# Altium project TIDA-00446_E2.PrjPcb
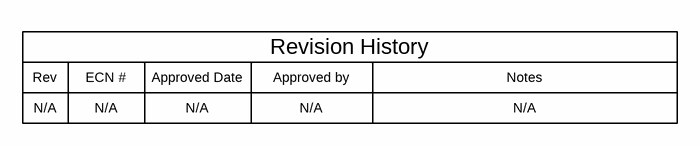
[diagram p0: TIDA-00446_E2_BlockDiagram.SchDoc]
CopyrightYear: 2015; EVM_Orderable: N/A; PCB_Layout: Avinash N; PCB_Rev: E2; PRJ_Customer: Public Release; PRJ_Engineer: Pawan N; PRJ_Number: TIDA-00446; PRJ_Title: 6 channel Isolated Gate driver; SCH_Rev: E2; TechSupport: http://www.ti.com/support; TID: TIDA-00446
5 sheets, 193 parts. Net scope: flat (ports and power ports of the same name join across sheets).
Board file: TIDA-00446_E2.PcbDoc
Sheets:
  TIDA-00446_E2_BlockDiagram.SchDoc
  TIDA-00446_E2_GateDriverPhaseU.SchDoc
  TIDA-00446_E2_GateDriverPhaseV.SchDoc
  TIDA-00446_E2_GateDriverPhaseW.SchDoc
  TIDA-00446_E2_TID_Hardware.SchDoc

## Sheet TIDA-00446_E2_BlockDiagram.SchDoc: Block Diagram
size 431 x 279 mm; Date: Not shown in title block; ApprovedBy: Not shown in title block; CheckedBy: Not shown in title block; Author: Not shown in title block; CompanyName: Not shown in title block; DrawnBy: Pawan N; Engineer: Not shown in title block; Organization: Not shown in title block; Address1: Not shown in title block; Address2: Not shown in title block; Address3: Not shown in title block; Address4: Not shown in title block; DocumentNumber: 1; Revision: Use project parameter SCH_Rev; SheetNumber: 1; SheetTotal: 5; PageSetup: Record=PageOptions¦CenterHorizontal=True¦CenterVertical=True¦PrintScale=1.00¦XCorrection=1.00¦YCorrection=1.00¦PrintKind=0¦BorderSize=5000000¦LeftOffset=0¦BottomOffset=0¦Orientation=2¦PaperLength=1000¦PaperWidth=1000¦Scale=100¦PaperSource=15¦PrintQuality=600¦MediaType=1¦DitherType=10¦PaperKind=Letter¦PrintScaleMode=1

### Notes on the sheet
- Rev
- N/A
- ECN #
- Approved Date
- Approved by
- Revision History
- Notes

## Sheet TIDA-00446_E2_GateDriverPhaseU.SchDoc: Power supply and Gate driver
size 431 x 279 mm; Date: Not shown in title block; ApprovedBy: Not shown in title block; CheckedBy: Not shown in title block; Author: Not shown in title block; CompanyName: Not shown in title block; DrawnBy: Pawan N; Engineer: Not shown in title block; Organization: Not shown in title block; Address1: Not shown in title block; Address2: Not shown in title block; Address3: Not shown in title block; Address4: Not shown in title block; DocumentNumber: 1; Revision: Use project parameter SCH_Rev; SheetNumber: 2; SheetTotal: 5; PageSetup: Record=PageOptions¦CenterHorizontal=True¦CenterVertical=True¦PrintScale=1.00¦XCorrection=1.00¦YCorrection=1.00¦PrintKind=0¦BorderSize=5000000¦LeftOffset=0¦BottomOffset=0¦Orientation=2¦PaperLength=1000¦PaperWidth=1000¦Scale=100¦PaperSource=15¦PrintQuality=600¦MediaType=1¦DitherType=10¦PaperKind=Letter¦PrintScaleMode=1
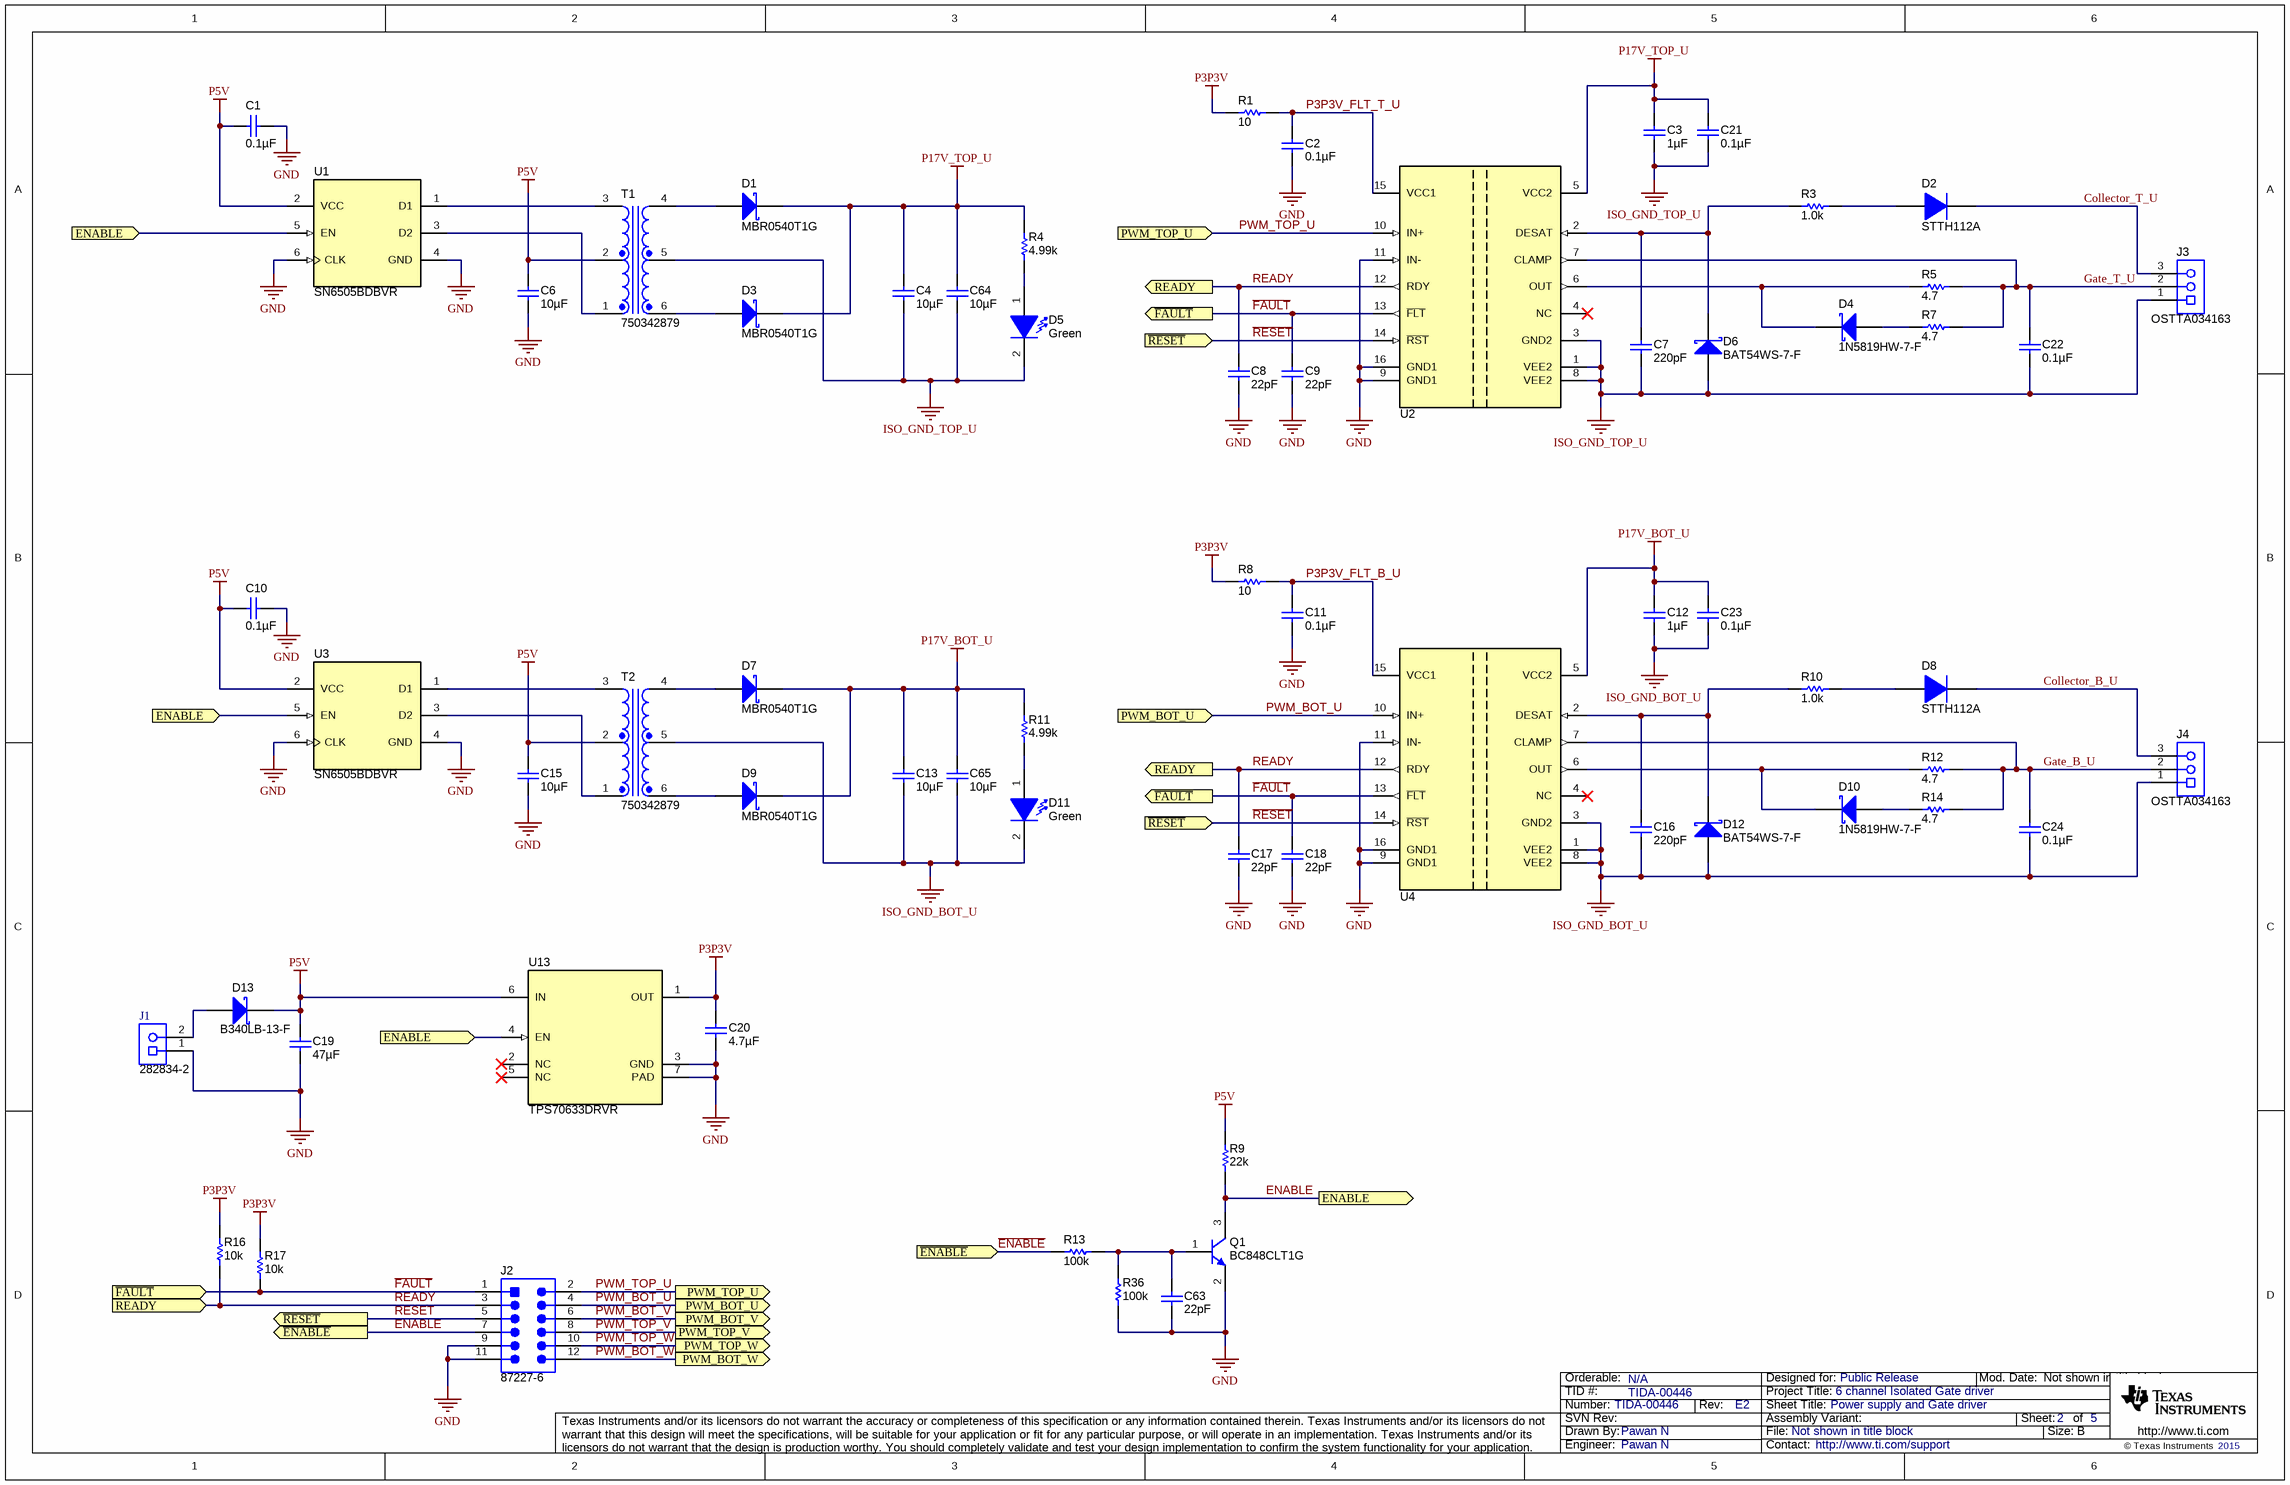
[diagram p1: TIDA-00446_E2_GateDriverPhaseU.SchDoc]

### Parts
C1  ValueDisplayed: 0.1µF  [0603]  (hidden comment: GRM188R71H104KA93D)
C2  ValueDisplayed: 0.1µF  [0603]  (hidden comment: GRM188R71H104KA93D)
C3  ValueDisplayed: 1µF  [0603]  (hidden comment: C1608X7R1V105K080AC)
C4  ValueDisplayed: 10µF  [1206_190]  (hidden comment: C3216X7R1V106K160AC)
C6  ValueDisplayed: 10µF  [0603]  (hidden comment: GRM188C81A106MA73D)
C7  ValueDisplayed: 220pF  [0402]  (hidden comment: C1005X7R1H104K050BB)
C8  ValueDisplayed: 22pF  [0402]  (hidden comment: GRM1555C1H220FA01D)
C9  ValueDisplayed: 22pF  [0402]  (hidden comment: GRM1555C1H220FA01D)
C10  ValueDisplayed: 0.1µF  [0603]  (hidden comment: GRM188R71H104KA93D)
C11  ValueDisplayed: 0.1µF  [0603]  (hidden comment: GRM188R71H104KA93D)
C12  ValueDisplayed: 1µF  [0603]  (hidden comment: C1608X7R1V105K080AC)
C13  ValueDisplayed: 10µF  [1206_190]  (hidden comment: C3216X7R1V106K160AC)
C15  ValueDisplayed: 10µF  [0603]  (hidden comment: GRM188C81A106MA73D)
C16  ValueDisplayed: 220pF  [0402]  (hidden comment: GRM155R71H221KA01D)
C17  ValueDisplayed: 22pF  [0402]  (hidden comment: GRM1555C1H220FA01D)
C18  ValueDisplayed: 22pF  [0402]  (hidden comment: GRM1555C1H220FA01D)
C19  ValueDisplayed: 47µF  [1210]  (hidden comment: GRM32ER61C476ME15L)
C20  ValueDisplayed: 4.7µF  [0603]  (hidden comment: C1608X7S1A475K080AC)
C21  ValueDisplayed: 0.1µF  [0603]  (hidden comment: GRM188R71H104KA93D)
C22  ValueDisplayed: 0.1µF  [0603]  (hidden comment: GRM188R71H104KA93D)
C23  ValueDisplayed: 0.1µF  [0603]  (hidden comment: GRM188R71H104KA93D)
C24  ValueDisplayed: 0.1µF  [0603]  (hidden comment: GRM188R71H104KA93D)
C63  ValueDisplayed: 22pF  [0402]  (hidden comment: GRM1555C1H220FA01D)
C64  ValueDisplayed: 10µF  [1206_190]  (hidden comment: C3216X7R1V106K160AC)
C65  ValueDisplayed: 10µF  [1206_190]  (hidden comment: C3216X7R1V106K160AC)
D1  MBR0540T1G  [SOD-123]
D2  STTH112A  [SMA]
D3  MBR0540T1G  [SOD-123]
D4  1N5819HW-7-F  [SOD-123]
D5  value Green  [LG L29K_GREEN]  (hidden comment: LG L29K-G2J1-24-Z)
D6  BAT54WS-7-F  [sod-323]
D7  MBR0540T1G  [SOD-123]
D8  STTH112A  [SMA]
D9  MBR0540T1G  [SOD-123]
D10  1N5819HW-7-F  [SOD-123]
D11  value Green  [LG L29K_GREEN]  (hidden comment: LG L29K-G2J1-24-Z)
D12  BAT54WS-7-F  [sod-323]
D13  B340LB-13-F  [SMB]
J1  282834-2  [TEC_282834-2]
J2  87227-6  [CONN_87227-6]
J3  OSTTA034163  [On-Shore_OSTTA034163]
J4  OSTTA034163  [On-Shore_OSTTA034163]
Q1  BC848CLT1G  [SOT-23]
R1  ValueDisplayed: 10  [0402]  (hidden comment: CRCW040210R0JNED)
R3  ValueDisplayed: 1.0k  [0805_HV]  (hidden comment: CRCW08051K00JNEA)
R4  ValueDisplayed: 4.99k  [0402]  (hidden comment: CRCW04024K99FKED)
R5  ValueDisplayed: 4.7  [1206]  (hidden comment: RPC1206JT4R70)
R7  ValueDisplayed: 4.7  [0805_HV]  (hidden comment: RPC0805JT4R70)
R8  ValueDisplayed: 10  [0402]  (hidden comment: RC0402JR-070RL)
R9  ValueDisplayed: 22k  [0603]  (hidden comment: CRCW060322K0JNEA)
R10  ValueDisplayed: 1.0k  [0805_HV]  (hidden comment: CRCW08051K00JNEA)
R11  ValueDisplayed: 4.99k  [0402]  (hidden comment: CRCW04024K99FKED)
R12  ValueDisplayed: 4.7  [1206]  (hidden comment: RPC1206JT4R70)
R13  ValueDisplayed: 100k  [0603]  (hidden comment: CRCW0603100KJNEA)
R14  ValueDisplayed: 4.7  [0805_HV]  (hidden comment: RPC0805JT4R70)
R16  ValueDisplayed: 10k  [0402]  (hidden comment: CRCW040210R0JNED)
R17  ValueDisplayed: 10k  [0402]  (hidden comment: CRCW040210R0JNED)
R36  ValueDisplayed: 100k  [0603]  (hidden comment: CRCW0603100KJNEA)
T1  750342879  [Wurth_750342879]
T2  750342879  [Wurth_750342879]
U1  SN6505BDBVR  [DBV0006A_N]
U2  ISO5851DWR  [DW0016B_N]  (value not drawn)
U3  SN6505BDBVR  [DBV0006A_N]
U4  ISO5851DWR  [DW0016B_N]  (value not drawn)
U13  TPS70633DRVR  [DRV0006A]

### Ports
ENABLE (in), ENABLE (out), PWM_BOT_U (in), PWM_BOT_U (out), PWM_BOT_V (out), PWM_BOT_W (out), PWM_TOP_U (in), PWM_TOP_U (out), PWM_TOP_V (out), PWM_TOP_W (out), READY (in), READY (out), ~{ENABLE} (in), ~{ENABLE} (out), ~{FAULT} (in), ~{FAULT} (out), ~{RESET} (in), ~{RESET} (out)

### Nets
GND: C1.1 C2.2 C6.2 C8.2 C9.2 C10.1 C11.2 C15.2 C17.2 C18.2 C19.2 C20.2 C63.2 J1.1 J2.9 J2.11 Q1.2(E) R36.1 U1.4(GND) U1.6(CLK) U2.9(GND1) U2.11(IN-) U2.16(GND1) U3.4(GND) U3.6(CLK) U4.9(GND1) U4.11(IN-) U4.16(GND1) U13.3(GND) U13.7(PAD)
ISO_GND_BOT_U: C12.2 C13.2 C16.2 C23.2 C24.2 C65.2 D11.2(K) D12.2(A) J4.1 T2.5 U4.1(VEE2) U4.3(GND2) U4.8(VEE2)
ISO_GND_TOP_U: C3.2 C4.2 C7.2 C21.2 C22.2 C64.2 D5.2(K) D6.2(A) J3.1 T1.5 U2.1(VEE2) U2.3(GND2) U2.8(VEE2)
P3P3V: C20.1 R1.1 R8.1 R16.2 R17.2 U13.1(OUT)
P5V: C1.2 C6.1 C10.2 C15.1 C19.1 D13.1(K) R9.2 T1.2 T2.2 U1.2(VCC) U3.2(VCC) U13.6(IN)
P17V_BOT_U: C12.1 C13.1 C23.1 C65.1 D7.1(K) D9.1(K) R11.2 U4.5(VCC2)
P17V_TOP_U: C3.1 C4.1 C21.1 C64.1 D1.1(K) D3.1(K) R4.2 U2.5(VCC2)
~{FAULT}: C9.1 C18.1 J2.1 R17.1 U2.13(~{FLT}) U4.13(~{FLT}) ; port ~{FAULT}
~{RESET}: J2.5 U2.14(~{RST}) U4.14(~{RST}) ; port ~{RESET}
Collector_B_U: D8.1(K) J4.3
Collector_T_U: D2.1(K) J3.3
~{ENABLE}: J2.7 R13.1 ; port ~{ENABLE}
ENABLE: Q1.3(C) R9.1 U1.5(EN) U3.5(EN) U13.4(EN) ; port ENABLE
Gate_B_U: C24.1 J4.2 R12.2 R14.2 U4.7(CLAMP)
Gate_T_U: C22.1 J3.2 R5.2 R7.2 U2.7(CLAMP)
P3P3V_FLT_B_U: C11.1 R8.2 U4.15(VCC1)
P3P3V_FLT_T_U: C2.1 R1.2 U2.15(VCC1)
PWM_BOT_U: J2.4 U4.10(IN+) ; port PWM_BOT_U
PWM_BOT_V: J2.6 ; port PWM_BOT_V
PWM_BOT_W: J2.12 ; port PWM_BOT_W
PWM_TOP_U: J2.2 U2.10(IN+) ; port PWM_TOP_U
PWM_TOP_V: J2.8 ; port PWM_TOP_V
PWM_TOP_W: J2.10 ; port PWM_TOP_W
READY: C8.1 C17.1 J2.3 R16.1 U2.12(RDY) U4.12(RDY) ; port READY
NetC7_1: C7.1 D6.1(K) R3.1 U2.2(DESAT)
NetC16_1: C16.1 D12.1(K) R10.1 U4.2(DESAT)
NetC63_1: C63.1 Q1.1(B) R13.2 R36.2
NetD1_2: D1.2(A) T1.4
NetD2_2: D2.2(A) R3.2
NetD3_2: D3.2(A) T1.6
NetD4_1: D4.1(K) R5.1 U2.6(OUT)
NetD4_2: D4.2(A) R7.1
NetD5_1: D5.1(A) R4.1
NetD7_2: D7.2(A) T2.4
NetD8_2: D8.2(A) R10.2
NetD9_2: D9.2(A) T2.6
NetD10_1: D10.1(K) R12.1 U4.6(OUT)
NetD10_2: D10.2(A) R14.1
NetD11_1: D11.1(A) R11.1
NetD13_2: D13.2(A) J1.2
NetT1_1: T1.1 U1.3(D2)
NetT1_3: T1.3 U1.1(D1)
NetT2_1: T2.1 U3.3(D2)
NetT2_3: T2.3 U3.1(D1)

Not connected (* = marked no-connect by the designer): U2 4(NC)*; U4 4(NC)*; U13 2(NC)* 5(NC)*

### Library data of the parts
C1 C2 C10 C11 C21-C24 = GRM188R71H104KA93D: CAP, CERM, 0.1 µF, 50 V, +/- 10%, X7R, 0603; Manufacturer: MuRata; Polarized: N; CompType: Capacitor; Value: 0.1uF; U/M: EA; Cap_F: 0.0000001; Tolerance_%: 10; Value1: Unknown; VDC_V: 50; Value2: 50V; TaMin_C: -55; TaMax_C: 125
C3 C12 = C1608X7R1V105K080AC: CAP, CERM, 1 µF, 30 V, +/- 10%, X7R, 0603; Manufacturer: TDK; Polarized: N; CompType: Capacitor; Value: 1uF; U/M: EA; Cap_F: 0.000001; Tolerance_%: 10; Value1: Unknown; VDC_V: 30; Value2: 30V; TaMin_C: -55; TaMax_C: 125; AEC Category: Q200
C4 C13 C64 C65 = C3216X7R1V106K160AC: CAP, CERM, 10 µF, 35 V, +/- 10%, X7R, 1206_190; Manufacturer: TDK; Polarized: N; CompType: Capacitor; Value: 10uF; U/M: EA; Cap_F: 0.00001; Tolerance_%: 10; Value1: Unknown; VDC_V: 35; Value2: 35V; TaMin_C: -55; TaMax_C: 125; Cap_Case: 1206; AEC Category: Q200
C6 C15 = GRM188C81A106MA73D: CAP, CERM, 10 µF, 10 V, +/- 20%, X6S, 0603; Manufacturer: MuRata; Polarized: N; CompType: Capacitor; Value: 10uF; U/M: EA; Cap_F: 0.00001; Tolerance_%: 20; Value1: Unknown; VDC_V: 10; Value2: 10V; TaMin_C: -55; TaMax_C: 105; AEC Category: Q200
C7 C16 = GRM155R71H221KA01D: CAP, CERM, 220 pF, 50 V, +/- 10%, X7R, 0402; Manufacturer: MuRata; Polarized: N; CompType: Capacitor; Value: 220pF; U/M: EA; Cap_F: 0.00000000022; Tolerance_%: 10; Value1: Unknown; VDC_V: 50; Value2: 50V; TaMin_C: -55; TaMax_C: 125
C8 C9 C17 C18 C63 = GRM1555C1H220FA01D: CAP, CERM, 22 pF, 50 V, +/- 1%, C0G/NP0, 0402; Manufacturer: MuRata; Polarized: N; CompType: Capacitor; Value: 22pF; U/M: EA; Cap_F: 0.000000000022; Tolerance_%: 1; Value1: Unknown; VDC_V: 50; Value2: 50V; TaMin_C: -55; TaMax_C: 125; AEC Category: Q200
C19 = GRM32ER61C476ME15L: CAP, CERM, 47 µF, 16 V, +/- 20%, X5R, 1210; Manufacturer: MuRata; Polarized: N; CompType: Capacitor; Value: 47uF; U/M: EA; Cap_F: 0.000047; Tolerance_%: 20; ESR_ohm: 0.002; Value1: 0.002 ohm; VDC_V: 16; Value2: 16V; TaMin_C: -55; TaMax_C: 85; AEC Category: Q200
C20 = C1608X7S1A475K080AC: CAP, CERM, 4.7 µF, 10 V, +/- 10%, X7S, 0603; Manufacturer: TDK; Polarized: N; CompType: Capacitor; Value: 4.7uF; U/M: EA; Cap_F: 0.0000047; Tolerance_%: 10; Value1: Unknown; Value2: 10V; TaMin_C: -55; TaMax_C: 125; AEC Category: Q200
D1 D3 D7 D9 = MBR0540T1G: Diode, Schottky, 40 V, 0.5 A, SOD-123; Manufacturer: ON Semiconductor; U/M: EA; Vf_V: 0.51; Value: 40V; Value1: 0.5A; Value2: 0.51V; Io_A: 0.5; Vr_V: 40; TJmax_C: 150; RJC_CperW: 118
D2 D8 = STTH112A: Diode, Ultrafast, 1200 V, 1 A, SMA; Manufacturer: STMicroelectronics; U/M: EA; Vf_V: 1.9; Value: 1200V; Value1: 1A; Value2: 1.9V; Io_A: 1; Vr_V: 1200; TJmax_C: 175; AEC Category: Q101; AEC Qualified: N
D4 D10 = 1N5819HW-7-F: Diode, Schottky, 40 V, 1 A, SOD-123; Manufacturer: Diodes Inc.; U/M: EA; Vf_V: 0.45; Value: 40V; Value1: 1A; Value2: 0.45V; Io_A: 1; Vr_V: 40; TJmax_C: 125
D5 D11 = LG L29K-G2J1-24-Z: LED, Green, SMD; Manufacturer: OSRAM; Vf_V: 1.7; Value2: 1.7V; Io_A: 0.002; Tjmax_C: 110; Value1: W; U/M: EA
D6 D12 = BAT54WS-7-F: Diode, Schottky, 30 V, 0.2 A, SOD-323; Manufacturer: Diodes Inc.; U/M: EA; Vf_V: 0.7; Value: 30V; Value1: 0.2A; Value2: 0.7V; Io_A: 0.2; Vr_V: 30; TJmax_C: 125
D13 = B340LB-13-F: Diode, Schottky, 40 V, 3 A, SMB; Manufacturer: Diodes Inc.; U/M: EA; Vf_V: 0.45; Value: 40V; Value1: 3A; Value2: 0.45V; Io_A: 3; Vr_V: 40; TJmax_C: 125; RJC_CperW: 25; AEC Category: Q101
J1 = 282834-2: Terminal Block, 2x1, 2.54mm, TH; Manufacturer: TE Connectivity; SymbolCreator: a0412235; U/M: EA
J2 = 87227-6: Header, 100mil, 6x2, Gold, TH; Manufacturer: TE Connectivity; SymbolCreator: a0412235; U/M: EA
J3 J4 = OSTTA034163: Terminal Block, 3x1, 5.08 mm, TH; Manufacturer: On-Shore Technology; SymbolCreator: a0412235; U/M: EA
Q1 = BC848CLT1G, ON Semiconductor: Transistor, NPN, 30 V, 0.1 A, SOT-23; CompType: BJT; PNP: 0; NPN: 1; Vceo_V: 30; Vcesat1_V: 0.7; Value: 30 V; IcRated_A: 0.1; Value1: 0.1 A; HfeMax: 800; TaMin_C: -55; TaMax_C: 150; U/M: EA
R1 R8 = CRCW040210R0JNED: RES, 10, 5%, 0.063 W, 0402; Manufacturer: Vishay-Dale; CompType: Resistor; Value: 10; Value_Code: 10R0; Tolerance_%: 5; Power_W: 0.063; Value2: 0.063W; VDC_V: 50; TempCo: 200 ppm/C; EIA_Code: E24; U/M: EA
R3 R10 = CRCW08051K00JNEA: RES, 1.0 k, 5%, 0.125 W, 0805; Manufacturer: Vishay-Dale; CompType: Resistor; Value: 1.0k; Res_ohm: 1000; Value_Code: 1k00; Tolerance_%: 5; Power_W: 0.125; Value2: 0.125W; VDC_V: 150; TempCo: 200 ppm/C; EIA_Code: E24; U/M: EA
R4 R11 = CRCW04024K99FKED: RES, 4.99 k, 1%, 0.063 W, 0402; Manufacturer: Vishay-Dale; CompType: Resistor; Value: 4.99k; Res_ohm: 4990; Value_Code: 4k99; Tolerance_%: 1; Power_W: 0.063; Value2: 0.063W; VDC_V: 50; TempCo: 100 ppm/C; EIA_Code: E96; U/M: EA
R5 R12 = RPC1206JT4R70: RES, 4.7, 5%, 0.33 W, 1206; Manufacturer: Stackpole Electronics Inc; CompType: Resistor; Value: 4.7; Value_Code: 4R70; Tolerance_%: 5; Power_W: 0.33; Value2: 0.33W; TempCo: 200 ppm/C; EIA_Code: E24; U/M: EA; AEC Category: Q200; AEC Qualified: N
R7 R14 = RPC0805JT4R70: RES, 4.7, 5%, 0.25 W, 0805; Manufacturer: Stackpole Electronics Inc; CompType: Resistor; Value: 4.7; Value_Code: 4R70; Tolerance_%: 5; Power_W: 0.25; Value2: 0.25W; TempCo: 200 ppm/C; EIA_Code: E24; U/M: EA; AEC Category: Q200; AEC Qualified: N
R9 = CRCW060322K0JNEA: RES, 22 k, 5%, 0.1 W, 0603; Manufacturer: Vishay-Dale; CompType: Resistor; Value: 22k; Res_ohm: 22000; Value_Code: 22k0; Tolerance_%: 5; Power_W: 0.1; Value2: 0.1W; VDC_V: 75; TempCo: 200 ppm/C; EIA_Code: E24; U/M: EA
R13 R36 = CRCW0603100KJNEA: RES, 100 k, 5%, 0.1 W, 0603; Manufacturer: Vishay-Dale; CompType: Resistor; Value: 100k; Res_ohm: 100000; Tolerance_%: 5; Power_W: 0.1; Value2: 0.1W; VDC_V: 75; TempCo: 200 ppm/C; EIA_Code: E24; U/M: EA; AEC Category: Q200
R16 R17 = CRCW040210K0JNED: RES, 10 k, 5%, 0.063 W, 0402; Manufacturer: Vishay-Dale; CompType: Resistor; Value: 10k; Res_ohm: 10000; Value_Code: 10k0; Tolerance_%: 5; Power_W: 0.063; Value2: 0.063W; VDC_V: 50; TempCo: 200 ppm/C; EIA_Code: E24; U/M: EA
T1 T2 = 750342879: Transformer, 50 uH, SMT; Manufacturer: Wurth Elektronik; SymbolCreator: Altium; Value: 50 uH; U/M: EA
U1 U3 = SN6505BDBVR: LOW-NOISE 1A TRANSFORMER DRIVERS FOR ISOLATED POWER SUPPLIES, DBV0006A; Alternate PartNumber: SN6505BDBVT; Manufacturer: Texas Instruments; SymbolCreator: Altium; CompType: IC; U/M: EA
U2 U4 = ISO5851DWR: High-CMTI 2.5-A / 5-A Isolated IGBT, MOSFET Gate Driver with Active Safety Features, DW0016B; Manufacturer: Texas Instruments; SymbolCreator: Altium; CompType: IC; U/M: EA
U13 = TPS70633DRVR: 150-mA, 6.5-V, 1-uA IQ Voltage Regulators with Enable, DRV0006A; Alternate PartNumber: TPS70633DRVT; Manufacturer: Texas Instruments; SymbolCreator: Altium; CompType: IC; U/M: EA

## Sheet TIDA-00446_E2_GateDriverPhaseV.SchDoc: Power supply and Gate driver
size 431 x 279 mm; Date: Not shown in title block; ApprovedBy: Not shown in title block; CheckedBy: Not shown in title block; Author: Not shown in title block; CompanyName: Not shown in title block; DrawnBy: Pawan N; Engineer: Not shown in title block; Organization: Not shown in title block; Address1: Not shown in title block; Address2: Not shown in title block; Address3: Not shown in title block; Address4: Not shown in title block; DocumentNumber: 1; Revision: Use project parameter SCH_Rev; SheetNumber: 3; SheetTotal: 5; PageSetup: Record=PageOptions¦CenterHorizontal=True¦CenterVertical=True¦PrintScale=1.00¦XCorrection=1.00¦YCorrection=1.00¦PrintKind=0¦BorderSize=5000000¦LeftOffset=0¦BottomOffset=0¦Orientation=2¦PaperLength=1000¦PaperWidth=1000¦Scale=100¦PaperSource=15¦PrintQuality=600¦MediaType=1¦DitherType=10¦PaperKind=Letter¦PrintScaleMode=1
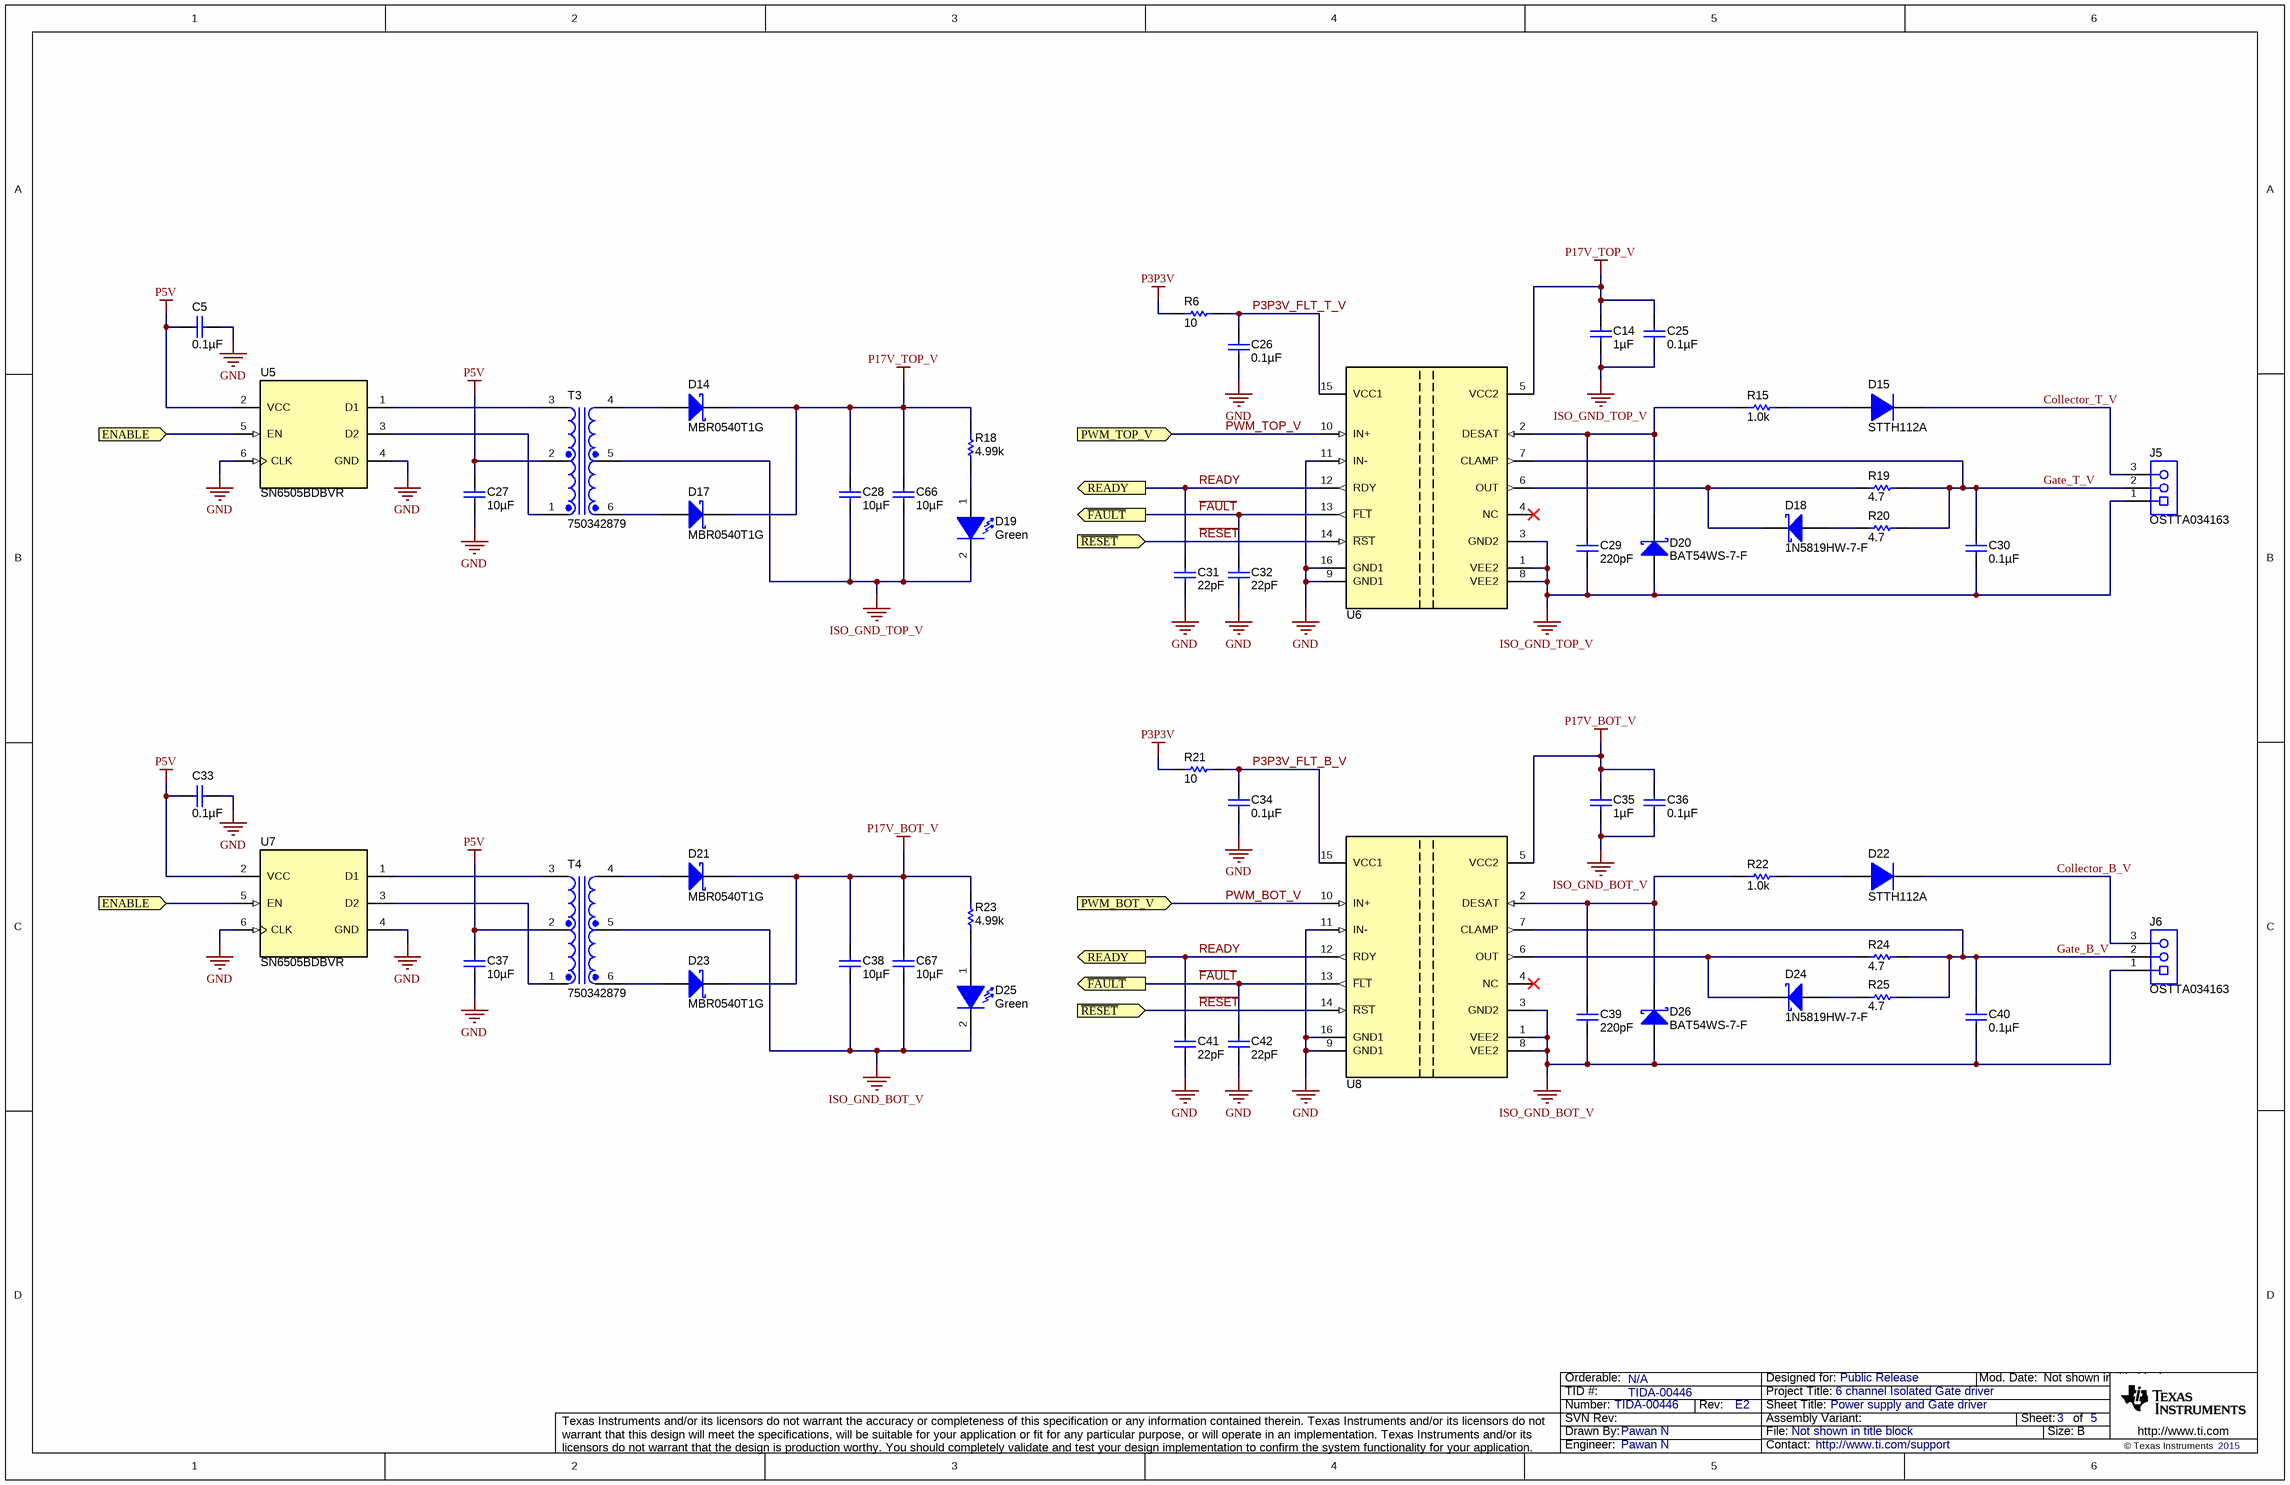
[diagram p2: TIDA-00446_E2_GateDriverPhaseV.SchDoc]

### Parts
C5  ValueDisplayed: 0.1µF  [0603]  (hidden comment: GRM188R71H104KA93D)
C14  ValueDisplayed: 1µF  [0603]  (hidden comment: C1608X7R1V105K080AC)
C25  ValueDisplayed: 0.1µF  [0603]  (hidden comment: GRM188R71H104KA93D)
C26  ValueDisplayed: 0.1µF  [0603]  (hidden comment: GRM188R71H104KA93D)
C27  ValueDisplayed: 10µF  [0603]  (hidden comment: GRM188C81A106MA73D)
C28  ValueDisplayed: 10µF  [1206_190]  (hidden comment: C3216X7R1V106K160AC)
C29  ValueDisplayed: 220pF  [0402]  (hidden comment: C1005X7R1H104K050BB)
C30  ValueDisplayed: 0.1µF  [0603]  (hidden comment: GRM188R71H104KA93D)
C31  ValueDisplayed: 22pF  [0402]  (hidden comment: GRM1555C1H220FA01D)
C32  ValueDisplayed: 22pF  [0402]  (hidden comment: GRM1555C1H220FA01D)
C33  ValueDisplayed: 0.1µF  [0603]  (hidden comment: GRM188R71H104KA93D)
C34  ValueDisplayed: 0.1µF  [0603]  (hidden comment: GRM188R71H104KA93D)
C35  ValueDisplayed: 1µF  [0603]  (hidden comment: C1608X7R1V105K080AC)
C36  ValueDisplayed: 0.1µF  [0603]  (hidden comment: GRM188R71H104KA93D)
C37  ValueDisplayed: 10µF  [0603]  (hidden comment: GRM188C81A106MA73D)
C38  ValueDisplayed: 10µF  [1206_190]  (hidden comment: C3216X7R1V106K160AC)
C39  ValueDisplayed: 220pF  [0402]  (hidden comment: GRM155R71H221KA01D)
C40  ValueDisplayed: 0.1µF  [0603]  (hidden comment: GRM188R71H104KA93D)
C41  ValueDisplayed: 22pF  [0402]  (hidden comment: GRM1555C1H220FA01D)
C42  ValueDisplayed: 22pF  [0402]  (hidden comment: GRM1555C1H220FA01D)
C66  ValueDisplayed: 10µF  [1206_190]  (hidden comment: C3216X7R1V106K160AC)
C67  ValueDisplayed: 10µF  [1206_190]  (hidden comment: C3216X7R1V106K160AC)
D14  MBR0540T1G  [SOD-123]
D15  STTH112A  [SMA]
D17  MBR0540T1G  [SOD-123]
D18  1N5819HW-7-F  [SOD-123]
D19  value Green  [LG L29K_GREEN]  (hidden comment: LG L29K-G2J1-24-Z)
D20  BAT54WS-7-F  [sod-323]
D21  MBR0540T1G  [SOD-123]
D22  STTH112A  [SMA]
D23  MBR0540T1G  [SOD-123]
D24  1N5819HW-7-F  [SOD-123]
D25  value Green  [LG L29K_GREEN]  (hidden comment: LG L29K-G2J1-24-Z)
D26  BAT54WS-7-F  [sod-323]
J5  OSTTA034163  [On-Shore_OSTTA034163]
J6  OSTTA034163  [On-Shore_OSTTA034163]
R6  ValueDisplayed: 10  [0402]  (hidden comment: CRCW040210R0JNED)
R15  ValueDisplayed: 1.0k  [0805_HV]  (hidden comment: CRCW08051K00JNEA)
R18  ValueDisplayed: 4.99k  [0402]  (hidden comment: CRCW04024K99FKED)
R19  ValueDisplayed: 4.7  [1206]  (hidden comment: RPC1206JT4R70)
R20  ValueDisplayed: 4.7  [0805_HV]  (hidden comment: RPC0805JT4R70)
R21  ValueDisplayed: 10  [0402]  (hidden comment: RC0402JR-070RL)
R22  ValueDisplayed: 1.0k  [0805_HV]  (hidden comment: CRCW08051K00JNEA)
R23  ValueDisplayed: 4.99k  [0402]  (hidden comment: CRCW04024K99FKED)
R24  ValueDisplayed: 4.7  [1206]  (hidden comment: RPC1206JT4R70)
R25  ValueDisplayed: 4.7  [0805_HV]  (hidden comment: RPC0805JT4R70)
T3  750342879  [Wurth_750342879]
T4  750342879  [Wurth_750342879]
U5  SN6505BDBVR  [DBV0006A_N]
U6  ISO5851DWR  [DW0016B_N]  (value not drawn)
U7  SN6505BDBVR  [DBV0006A_N]
U8  ISO5851DWR  [DW0016B_N]  (value not drawn)

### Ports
ENABLE (in), PWM_BOT_V (in), PWM_TOP_V (in), READY (out), ~{FAULT} (out), ~{RESET} (in)

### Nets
GND: C5.1 C26.2 C27.2 C31.2 C32.2 C33.1 C34.2 C37.2 C41.2 C42.2 U5.4(GND) U5.6(CLK) U6.9(GND1) U6.11(IN-) U6.16(GND1) U7.4(GND) U7.6(CLK) U8.9(GND1) U8.11(IN-) U8.16(GND1)
ISO_GND_BOT_V: C35.2 C36.2 C38.2 C39.2 C40.2 C67.2 D25.2(K) D26.2(A) J6.1 T4.5 U8.1(VEE2) U8.3(GND2) U8.8(VEE2)
ISO_GND_TOP_V: C14.2 C25.2 C28.2 C29.2 C30.2 C66.2 D19.2(K) D20.2(A) J5.1 T3.5 U6.1(VEE2) U6.3(GND2) U6.8(VEE2)
P3P3V: R6.1 R21.1
P5V: C5.2 C27.1 C33.2 C37.1 T3.2 T4.2 U5.2(VCC) U7.2(VCC)
P17V_BOT_V: C35.1 C36.1 C38.1 C67.1 D21.1(K) D23.1(K) R23.2 U8.5(VCC2)
P17V_TOP_V: C14.1 C25.1 C28.1 C66.1 D14.1(K) D17.1(K) R18.2 U6.5(VCC2)
~{FAULT}: C32.1 C42.1 U6.13(~{FLT}) U8.13(~{FLT}) ; port ~{FAULT}
~{RESET}: U6.14(~{RST}) U8.14(~{RST}) ; port ~{RESET}
Collector_B_V: D22.1(K) J6.3
Collector_T_V: D15.1(K) J5.3
ENABLE: U5.5(EN) U7.5(EN) ; port ENABLE
Gate_B_V: C40.1 J6.2 R24.2 R25.2 U8.7(CLAMP)
Gate_T_V: C30.1 J5.2 R19.2 R20.2 U6.7(CLAMP)
P3P3V_FLT_B_V: C34.1 R21.2 U8.15(VCC1)
P3P3V_FLT_T_V: C26.1 R6.2 U6.15(VCC1)
PWM_BOT_V: U8.10(IN+) ; port PWM_BOT_V
PWM_TOP_V: U6.10(IN+) ; port PWM_TOP_V
READY: C31.1 C41.1 U6.12(RDY) U8.12(RDY) ; port READY
NetC29_1: C29.1 D20.1(K) R15.1 U6.2(DESAT)
NetC39_1: C39.1 D26.1(K) R22.1 U8.2(DESAT)
NetD14_2: D14.2(A) T3.4
NetD15_2: D15.2(A) R15.2
NetD17_2: D17.2(A) T3.6
NetD18_1: D18.1(K) R19.1 U6.6(OUT)
NetD18_2: D18.2(A) R20.1
NetD19_1: D19.1(A) R18.1
NetD21_2: D21.2(A) T4.4
NetD22_2: D22.2(A) R22.2
NetD23_2: D23.2(A) T4.6
NetD24_1: D24.1(K) R24.1 U8.6(OUT)
NetD24_2: D24.2(A) R25.1
NetD25_1: D25.1(A) R23.1
NetT3_1: T3.1 U5.3(D2)
NetT3_3: T3.3 U5.1(D1)
NetT4_1: T4.1 U7.3(D2)
NetT4_3: T4.3 U7.1(D1)

Not connected (* = marked no-connect by the designer): U6 4(NC)*; U8 4(NC)*

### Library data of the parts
C5 C25 C26 C30 C33 C34 C36 C40 = GRM188R71H104KA93D: as C1 on sheet TIDA-00446_E2_GateDriverPhaseU
C14 C35 = C1608X7R1V105K080AC: as C3 on sheet TIDA-00446_E2_GateDriverPhaseU
C27 C37 = GRM188C81A106MA73D: as C6 on sheet TIDA-00446_E2_GateDriverPhaseU
C28 C38 C66 C67 = C3216X7R1V106K160AC: as C4 on sheet TIDA-00446_E2_GateDriverPhaseU
C29 C39 = GRM155R71H221KA01D: as C7 on sheet TIDA-00446_E2_GateDriverPhaseU
C31 C32 C41 C42 = GRM1555C1H220FA01D: as C8 on sheet TIDA-00446_E2_GateDriverPhaseU
D14 D17 D21 D23 = MBR0540T1G: as D1 on sheet TIDA-00446_E2_GateDriverPhaseU
D15 D22 = STTH112A: as D2 on sheet TIDA-00446_E2_GateDriverPhaseU
D18 D24 = 1N5819HW-7-F: as D4 on sheet TIDA-00446_E2_GateDriverPhaseU
D19 D25 = LG L29K-G2J1-24-Z: as D5 on sheet TIDA-00446_E2_GateDriverPhaseU
D20 D26 = BAT54WS-7-F: as D6 on sheet TIDA-00446_E2_GateDriverPhaseU
J5 J6 = OSTTA034163: as J3 on sheet TIDA-00446_E2_GateDriverPhaseU
R6 R21 = CRCW040210R0JNED: as R1 on sheet TIDA-00446_E2_GateDriverPhaseU
R15 R22 = CRCW08051K00JNEA: as R3 on sheet TIDA-00446_E2_GateDriverPhaseU
R18 R23 = CRCW04024K99FKED: as R4 on sheet TIDA-00446_E2_GateDriverPhaseU
R19 R24 = RPC1206JT4R70: as R5 on sheet TIDA-00446_E2_GateDriverPhaseU
R20 R25 = RPC0805JT4R70: as R7 on sheet TIDA-00446_E2_GateDriverPhaseU
T3 T4 = 750342879: as T1 on sheet TIDA-00446_E2_GateDriverPhaseU
U5 U7 = SN6505BDBVR: as U1 on sheet TIDA-00446_E2_GateDriverPhaseU
U6 U8 = ISO5851DWR: as U2 on sheet TIDA-00446_E2_GateDriverPhaseU

## Sheet TIDA-00446_E2_GateDriverPhaseW.SchDoc: Power supply and Gate driver
size 431 x 279 mm; Date: Not shown in title block; ApprovedBy: Not shown in title block; CheckedBy: Not shown in title block; Author: Not shown in title block; CompanyName: Not shown in title block; DrawnBy: Pawan N; Engineer: Not shown in title block; Organization: Not shown in title block; Address1: Not shown in title block; Address2: Not shown in title block; Address3: Not shown in title block; Address4: Not shown in title block; DocumentNumber: 1; Revision: Use project parameter SCH_Rev; SheetNumber: 4; SheetTotal: 5; PageSetup: Record=PageOptions¦CenterHorizontal=True¦CenterVertical=True¦PrintScale=1.00¦XCorrection=1.00¦YCorrection=1.00¦PrintKind=0¦BorderSize=5000000¦LeftOffset=0¦BottomOffset=0¦Orientation=2¦PaperLength=1000¦PaperWidth=1000¦Scale=100¦PaperSource=15¦PrintQuality=600¦MediaType=1¦DitherType=10¦PaperKind=Letter¦PrintScaleMode=1
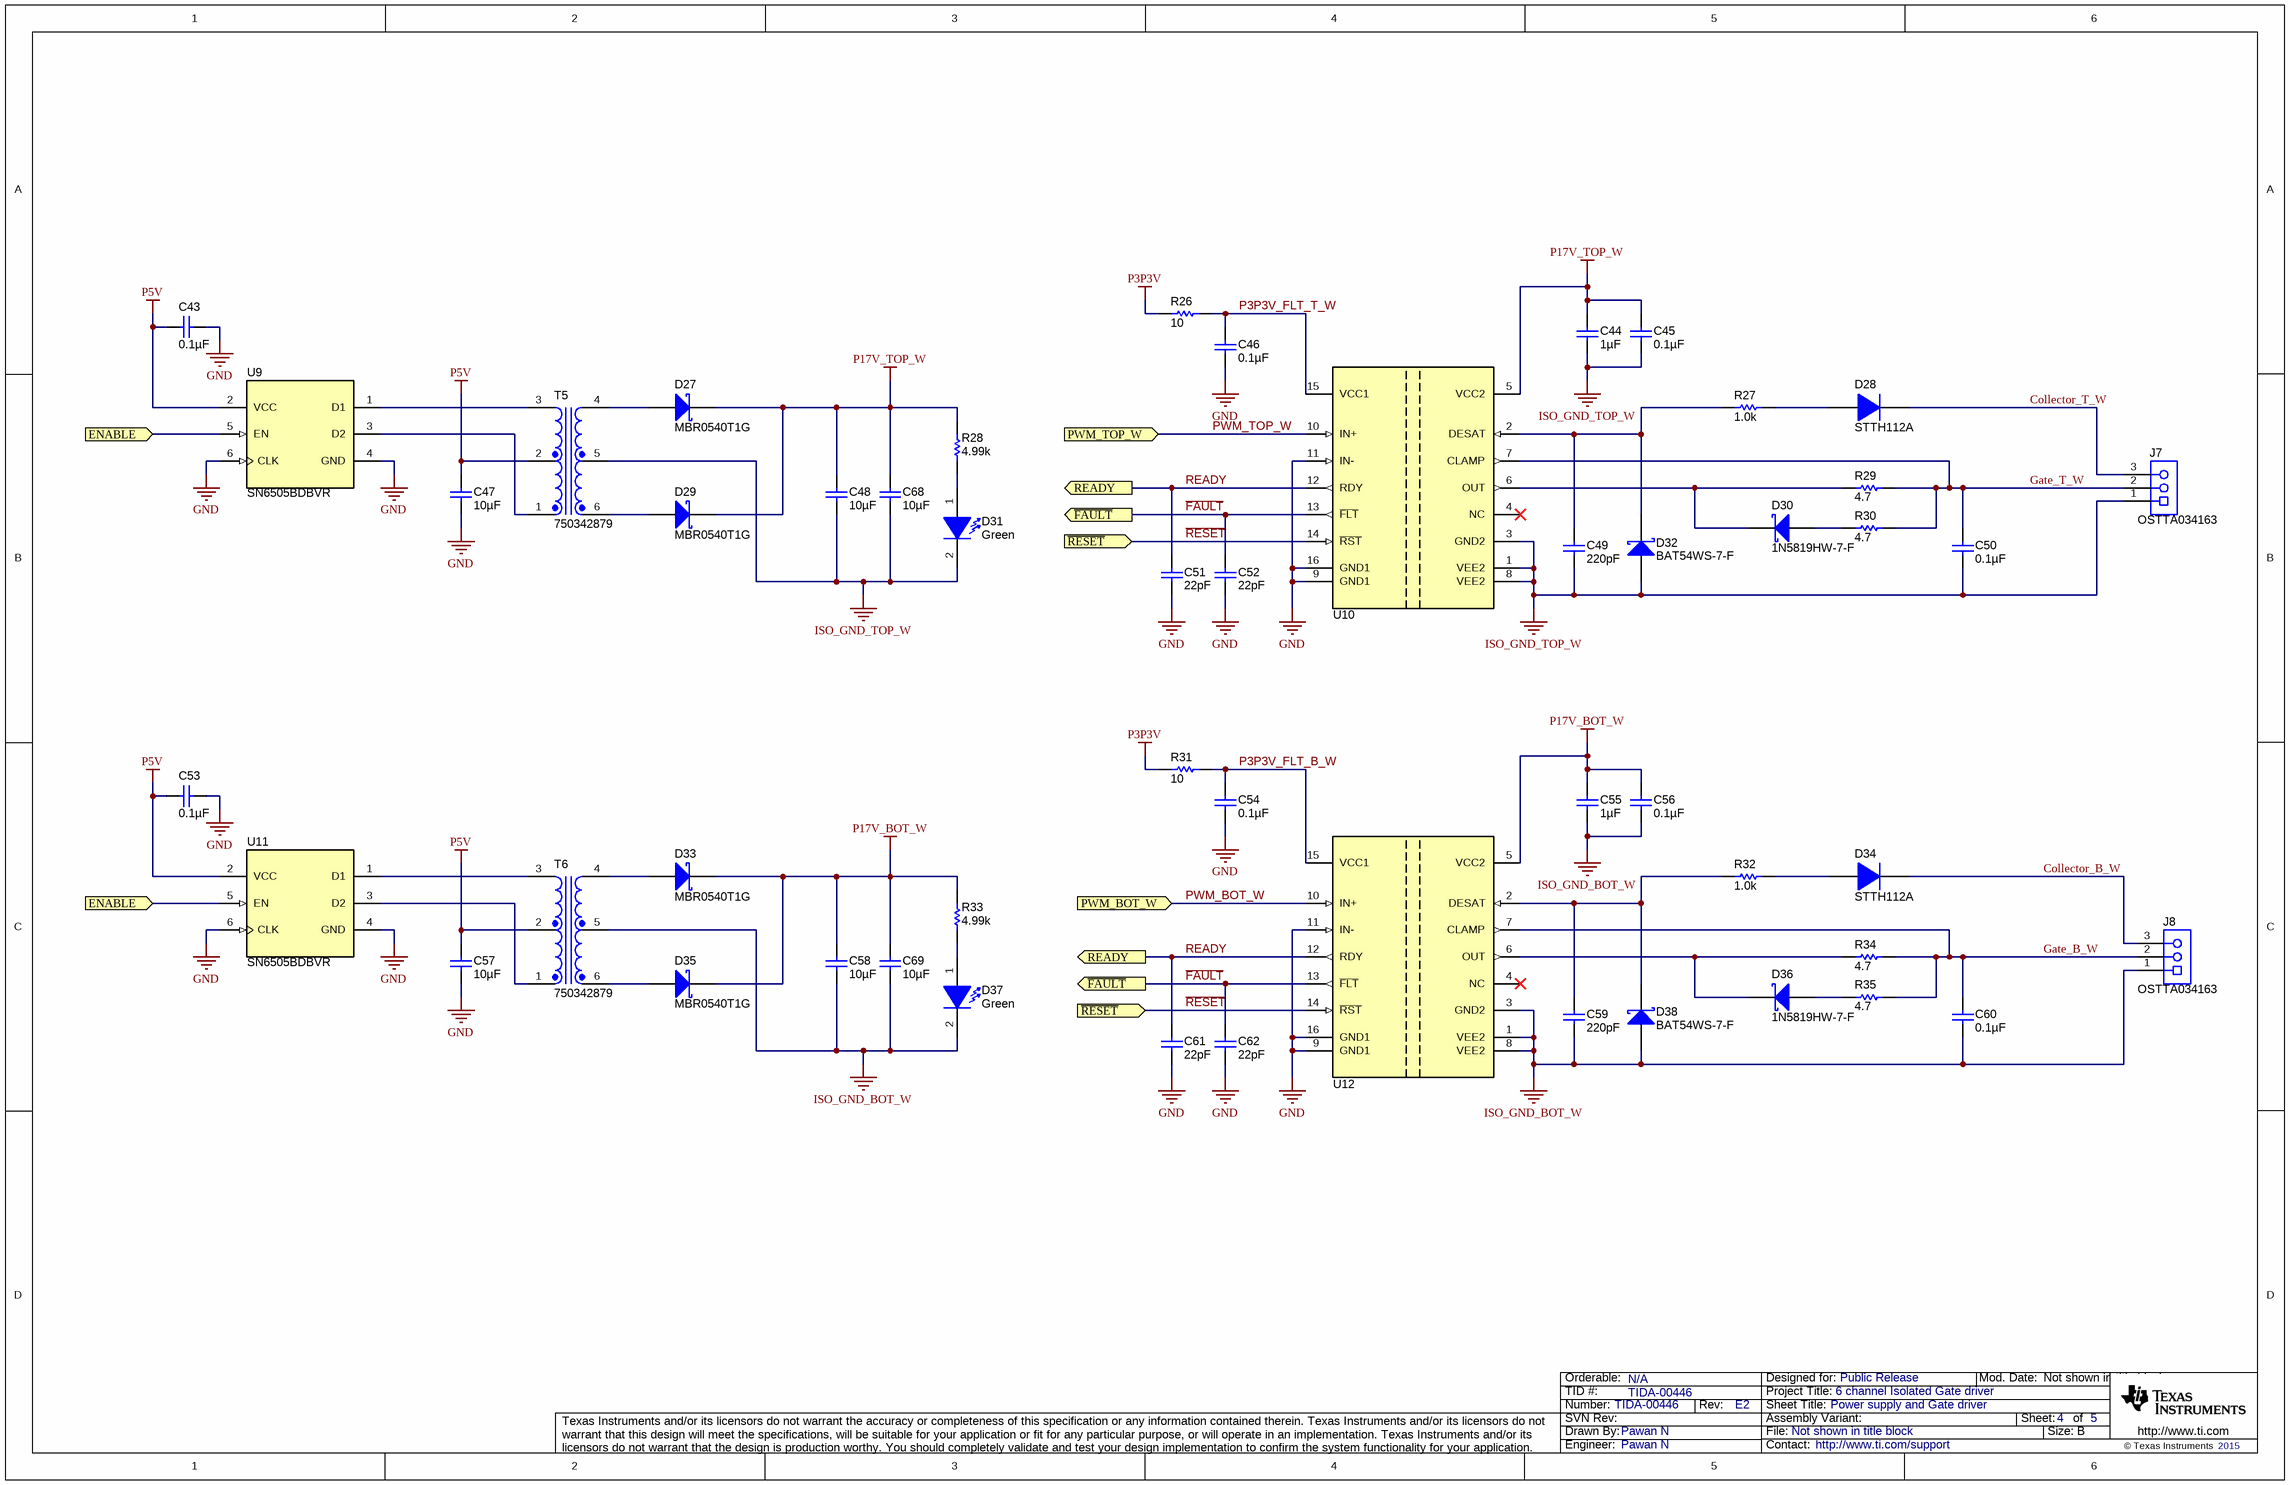
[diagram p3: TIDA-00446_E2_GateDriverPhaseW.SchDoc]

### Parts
C43  ValueDisplayed: 0.1µF  [0603]  (hidden comment: GRM188R71H104KA93D)
C44  ValueDisplayed: 1µF  [0603]  (hidden comment: C1608X7R1V105K080AC)
C45  ValueDisplayed: 0.1µF  [0603]  (hidden comment: GRM188R71H104KA93D)
C46  ValueDisplayed: 0.1µF  [0603]  (hidden comment: GRM188R71H104KA93D)
C47  ValueDisplayed: 10µF  [0603]  (hidden comment: GRM188C81A106MA73D)
C48  ValueDisplayed: 10µF  [1206_190]  (hidden comment: C3216X7R1V106K160AC)
C49  ValueDisplayed: 220pF  [0402]  (hidden comment: C1005X7R1H104K050BB)
C50  ValueDisplayed: 0.1µF  [0603]  (hidden comment: GRM188R71H104KA93D)
C51  ValueDisplayed: 22pF  [0402]  (hidden comment: GRM1555C1H220FA01D)
C52  ValueDisplayed: 22pF  [0402]  (hidden comment: GRM1555C1H220FA01D)
C53  ValueDisplayed: 0.1µF  [0603]  (hidden comment: GRM188R71H104KA93D)
C54  ValueDisplayed: 0.1µF  [0603]  (hidden comment: GRM188R71H104KA93D)
C55  ValueDisplayed: 1µF  [0603]  (hidden comment: C1608X7R1V105K080AC)
C56  ValueDisplayed: 0.1µF  [0603]  (hidden comment: GRM188R71H104KA93D)
C57  ValueDisplayed: 10µF  [0603]  (hidden comment: GRM188C81A106MA73D)
C58  ValueDisplayed: 10µF  [1206_190]  (hidden comment: C3216X7R1V106K160AC)
C59  ValueDisplayed: 220pF  [0402]  (hidden comment: GRM155R71H221KA01D)
C60  ValueDisplayed: 0.1µF  [0603]  (hidden comment: GRM188R71H104KA93D)
C61  ValueDisplayed: 22pF  [0402]  (hidden comment: GRM1555C1H220FA01D)
C62  ValueDisplayed: 22pF  [0402]  (hidden comment: GRM1555C1H220FA01D)
C68  ValueDisplayed: 10µF  [1206_190]  (hidden comment: C3216X7R1V106K160AC)
C69  ValueDisplayed: 10µF  [1206_190]  (hidden comment: C3216X7R1V106K160AC)
D27  MBR0540T1G  [SOD-123]
D28  STTH112A  [SMA]
D29  MBR0540T1G  [SOD-123]
D30  1N5819HW-7-F  [SOD-123]
D31  value Green  [LG L29K_GREEN]  (hidden comment: LG L29K-G2J1-24-Z)
D32  BAT54WS-7-F  [sod-323]
D33  MBR0540T1G  [SOD-123]
D34  STTH112A  [SMA]
D35  MBR0540T1G  [SOD-123]
D36  1N5819HW-7-F  [SOD-123]
D37  value Green  [LG L29K_GREEN]  (hidden comment: LG L29K-G2J1-24-Z)
D38  BAT54WS-7-F  [sod-323]
J7  OSTTA034163  [On-Shore_OSTTA034163]
J8  OSTTA034163  [On-Shore_OSTTA034163]
R26  ValueDisplayed: 10  [0402]  (hidden comment: CRCW040210R0JNED)
R27  ValueDisplayed: 1.0k  [0805_HV]  (hidden comment: CRCW08051K00JNEA)
R28  ValueDisplayed: 4.99k  [0402]  (hidden comment: CRCW04024K99FKED)
R29  ValueDisplayed: 4.7  [1206]  (hidden comment: RPC1206JT4R70)
R30  ValueDisplayed: 4.7  [0805_HV]  (hidden comment: RPC0805JT4R70)
R31  ValueDisplayed: 10  [0402]  (hidden comment: RC0402JR-070RL)
R32  ValueDisplayed: 1.0k  [0805_HV]  (hidden comment: CRCW08051K00JNEA)
R33  ValueDisplayed: 4.99k  [0402]  (hidden comment: CRCW04024K99FKED)
R34  ValueDisplayed: 4.7  [1206]  (hidden comment: RPC1206JT4R70)
R35  ValueDisplayed: 4.7  [0805_HV]  (hidden comment: RPC0805JT4R70)
T5  750342879  [Wurth_750342879]
T6  750342879  [Wurth_750342879]
U9  SN6505BDBVR  [DBV0006A_N]
U10  ISO5851DWR  [DW0016B_N]  (value not drawn)
U11  SN6505BDBVR  [DBV0006A_N]
U12  ISO5851DWR  [DW0016B_N]  (value not drawn)

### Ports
ENABLE (in), PWM_BOT_W (in), PWM_TOP_W (in), READY (out), ~{FAULT} (out), ~{RESET} (in)

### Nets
GND: C43.1 C46.2 C47.2 C51.2 C52.2 C53.1 C54.2 C57.2 C61.2 C62.2 U9.4(GND) U9.6(CLK) U10.9(GND1) U10.11(IN-) U10.16(GND1) U11.4(GND) U11.6(CLK) U12.9(GND1) U12.11(IN-) U12.16(GND1)
ISO_GND_BOT_W: C55.2 C56.2 C58.2 C59.2 C60.2 C69.2 D37.2(K) D38.2(A) J8.1 T6.5 U12.1(VEE2) U12.3(GND2) U12.8(VEE2)
ISO_GND_TOP_W: C44.2 C45.2 C48.2 C49.2 C50.2 C68.2 D31.2(K) D32.2(A) J7.1 T5.5 U10.1(VEE2) U10.3(GND2) U10.8(VEE2)
P3P3V: R26.1 R31.1
P5V: C43.2 C47.1 C53.2 C57.1 T5.2 T6.2 U9.2(VCC) U11.2(VCC)
P17V_BOT_W: C55.1 C56.1 C58.1 C69.1 D33.1(K) D35.1(K) R33.2 U12.5(VCC2)
P17V_TOP_W: C44.1 C45.1 C48.1 C68.1 D27.1(K) D29.1(K) R28.2 U10.5(VCC2)
~{FAULT}: C52.1 C62.1 U10.13(~{FLT}) U12.13(~{FLT}) ; port ~{FAULT}
~{RESET}: U10.14(~{RST}) U12.14(~{RST}) ; port ~{RESET}
Collector_B_W: D34.1(K) J8.3
Collector_T_W: D28.1(K) J7.3
ENABLE: U9.5(EN) U11.5(EN) ; port ENABLE
Gate_B_W: C60.1 J8.2 R34.2 R35.2 U12.7(CLAMP)
Gate_T_W: C50.1 J7.2 R29.2 R30.2 U10.7(CLAMP)
P3P3V_FLT_B_W: C54.1 R31.2 U12.15(VCC1)
P3P3V_FLT_T_W: C46.1 R26.2 U10.15(VCC1)
PWM_BOT_W: U12.10(IN+) ; port PWM_BOT_W
PWM_TOP_W: U10.10(IN+) ; port PWM_TOP_W
READY: C51.1 C61.1 U10.12(RDY) U12.12(RDY) ; port READY
NetC49_1: C49.1 D32.1(K) R27.1 U10.2(DESAT)
NetC59_1: C59.1 D38.1(K) R32.1 U12.2(DESAT)
NetD27_2: D27.2(A) T5.4
NetD28_2: D28.2(A) R27.2
NetD29_2: D29.2(A) T5.6
NetD30_1: D30.1(K) R29.1 U10.6(OUT)
NetD30_2: D30.2(A) R30.1
NetD31_1: D31.1(A) R28.1
NetD33_2: D33.2(A) T6.4
NetD34_2: D34.2(A) R32.2
NetD35_2: D35.2(A) T6.6
NetD36_1: D36.1(K) R34.1 U12.6(OUT)
NetD36_2: D36.2(A) R35.1
NetD37_1: D37.1(A) R33.1
NetT5_1: T5.1 U9.3(D2)
NetT5_3: T5.3 U9.1(D1)
NetT6_1: T6.1 U11.3(D2)
NetT6_3: T6.3 U11.1(D1)

Not connected (* = marked no-connect by the designer): U10 4(NC)*; U12 4(NC)*

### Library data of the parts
C43 C45 C46 C50 C53 C54 C56 C60 = GRM188R71H104KA93D: as C1 on sheet TIDA-00446_E2_GateDriverPhaseU
C44 C55 = C1608X7R1V105K080AC: as C3 on sheet TIDA-00446_E2_GateDriverPhaseU
C47 C57 = GRM188C81A106MA73D: as C6 on sheet TIDA-00446_E2_GateDriverPhaseU
C48 C58 C68 C69 = C3216X7R1V106K160AC: as C4 on sheet TIDA-00446_E2_GateDriverPhaseU
C49 C59 = GRM155R71H221KA01D: as C7 on sheet TIDA-00446_E2_GateDriverPhaseU
C51 C52 C61 C62 = GRM1555C1H220FA01D: as C8 on sheet TIDA-00446_E2_GateDriverPhaseU
D27 D29 D33 D35 = MBR0540T1G: as D1 on sheet TIDA-00446_E2_GateDriverPhaseU
D28 D34 = STTH112A: as D2 on sheet TIDA-00446_E2_GateDriverPhaseU
D30 D36 = 1N5819HW-7-F: as D4 on sheet TIDA-00446_E2_GateDriverPhaseU
D31 D37 = LG L29K-G2J1-24-Z: as D5 on sheet TIDA-00446_E2_GateDriverPhaseU
D32 D38 = BAT54WS-7-F: as D6 on sheet TIDA-00446_E2_GateDriverPhaseU
J7 J8 = OSTTA034163: as J3 on sheet TIDA-00446_E2_GateDriverPhaseU
R26 R31 = CRCW040210R0JNED: as R1 on sheet TIDA-00446_E2_GateDriverPhaseU
R27 R32 = CRCW08051K00JNEA: as R3 on sheet TIDA-00446_E2_GateDriverPhaseU
R28 R33 = CRCW04024K99FKED: as R4 on sheet TIDA-00446_E2_GateDriverPhaseU
R29 R34 = RPC1206JT4R70: as R5 on sheet TIDA-00446_E2_GateDriverPhaseU
R30 R35 = RPC0805JT4R70: as R7 on sheet TIDA-00446_E2_GateDriverPhaseU
T5 T6 = 750342879: as T1 on sheet TIDA-00446_E2_GateDriverPhaseU
U9 U11 = SN6505BDBVR: as U1 on sheet TIDA-00446_E2_GateDriverPhaseU
U10 U12 = ISO5851DWR: as U2 on sheet TIDA-00446_E2_GateDriverPhaseU

## Sheet TIDA-00446_E2_TID_Hardware.SchDoc: Mechanical Hardware
size 431 x 279 mm; Date: Not shown in title block; ApprovedBy: Not shown in title block; CheckedBy: Not shown in title block; Author: Not shown in title block; CompanyName: Not shown in title block; DrawnBy: Pawan N; Engineer: Not shown in title block; Organization: Not shown in title block; Address1: Not shown in title block; Address2: Not shown in title block; Address3: Not shown in title block; Address4: Not shown in title block; DocumentNumber: 1; Revision: Use project parameter SCH_Rev; SheetNumber: 5; SheetTotal: 5; PageSetup: Record=PageOptions¦CenterHorizontal=True¦CenterVertical=True¦PrintScale=1.00¦XCorrection=1.00¦YCorrection=1.00¦PrintKind=0¦BorderSize=5000000¦LeftOffset=0¦BottomOffset=0¦Orientation=2¦PaperLength=1000¦PaperWidth=1000¦Scale=100¦PaperSource=15¦PrintQuality=600¦MediaType=1¦DitherType=10¦PaperKind=Letter¦PrintScaleMode=1
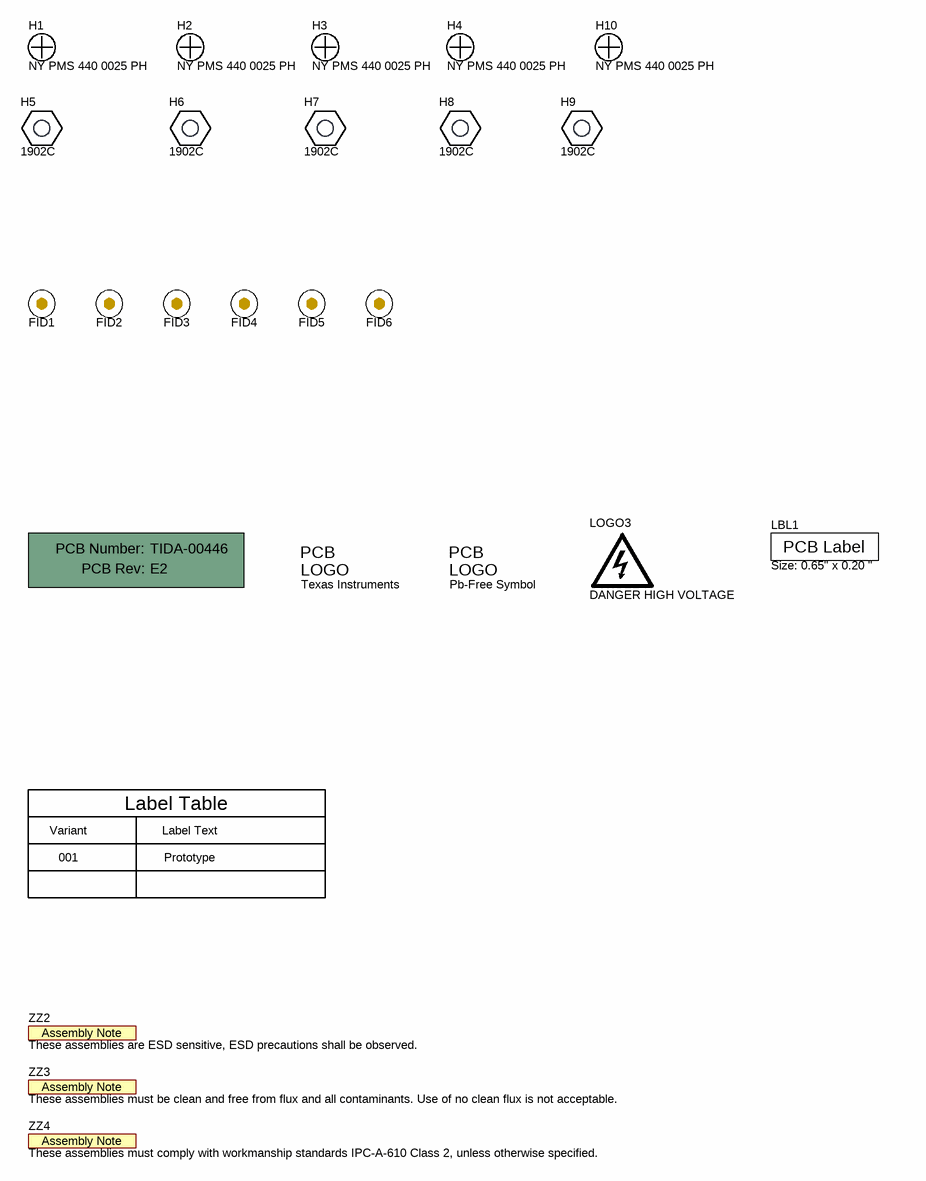
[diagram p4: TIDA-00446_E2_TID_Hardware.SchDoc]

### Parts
!PCB  Printed Circuit Board  [Label_650x200]  (value not drawn)  (mechanical)
FID1  Fiducial  [Fiducial10-20]  (value not drawn)
FID2  Fiducial  [Fiducial10-20]  (value not drawn)
FID3  Fiducial  [Fiducial10-20]  (value not drawn)
FID4  Fiducial  [Fiducial10-20]  (value not drawn)
FID5  Fiducial  [Fiducial10-20]  (value not drawn)
FID6  Fiducial  [Fiducial10-20]  (value not drawn)
H1  NY PMS 440 0025 PH  [NY PMS 440 0025 PH]
H2  NY PMS 440 0025 PH  [NY PMS 440 0025 PH]
H3  NY PMS 440 0025 PH  [NY PMS 440 0025 PH]
H4  NY PMS 440 0025 PH  [NY PMS 440 0025 PH]
H5  1902C  [Keystone_1902C]
H6  1902C  [Keystone_1902C]
H7  1902C  [Keystone_1902C]
H8  1902C  [Keystone_1902C]
H9  1902C  [Keystone_1902C]
H10  NY PMS 440 0025 PH  [NY PMS 440 0025 PH]
LBL1  Size: 0.65" x 0.20 "  [Label_650x200]
Logo1  Texas Instruments  [TI_Stacked_Overlay_Small]  (no BOM)
Logo2  Pb-Free Symbol  [Pb-Free_Overlay_Small]  (no BOM)
LOGO3  DANGER HIGH VOLTAGE  [IEC_HighVoltage_Small]  (no BOM)
ZZ2  These assemblies are ESD sensitive, ESD precautions shall be observed.  [AssemblyNote]  (no BOM)
ZZ3  These assemblies must be clean and free from flux and all contaminants. Use of no clean flux is not acceptable.  [AssemblyNote]  (no BOM)
ZZ4  These assemblies must comply with workmanship standards IPC-A-610 Class 2, unless otherwise specified.  [AssemblyNote]  (no BOM)

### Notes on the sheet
- Label Table
- Variant
- 001
- Label Text
- Prototype

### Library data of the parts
!PCB = PCB: Manufacturer: Any; PartNumber: TIDA-00446; SymbolCreator: a0412235
FID1-FID6 = Fiducial: Fiducial mark.  There is nothing to buy or mount.; SymbolCreator: codlsc
H1-H4 H10 = NY PMS 440 0025 PH: Machine Screw, Round, #4-40 x 1/4, Nylon, Philips panhead; Manufacturer: B&F Fastener Supply; CompType: Hardware; SymbolCreator: codlsc; U/M: EA
H5-H9 = 1902C: Standoff, Hex, 0.5"L #4-40 Nylon; Manufacturer: Keystone; CompType: Hardware
LBL1 = THT-14-423-10: Thermal Transfer Printable Labels, 0.650" W x 0.200" H - 10,000 per roll; Manufacturer: Brady; SymbolCreator: a0412235; CompType: Label
Logo1 = TI_Logo: Texas Instrument Corporate Signature; SymbolCreator: codlsc
Logo2 = Pb-Free: SymbolCreator: a0412235
LOGO3 = IEC_HighVoltage: IEC 61010-1 High Voltage Warning; SymbolCreator: a0412235
ZZ2-ZZ4 = AssemblyNote: SymbolCreator: codlsc

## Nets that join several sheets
GND: TIDA-00446_E2_GateDriverPhaseU (30 pins), TIDA-00446_E2_GateDriverPhaseV (20 pins), TIDA-00446_E2_GateDriverPhaseW (20 pins)
P3P3V: TIDA-00446_E2_GateDriverPhaseU (6 pins), TIDA-00446_E2_GateDriverPhaseV (R6.1 R21.1), TIDA-00446_E2_GateDriverPhaseW (R26.1 R31.1)
P5V: TIDA-00446_E2_GateDriverPhaseU (12 pins), TIDA-00446_E2_GateDriverPhaseV (8 pins), TIDA-00446_E2_GateDriverPhaseW (8 pins)
~{FAULT}: TIDA-00446_E2_GateDriverPhaseU (6 pins), TIDA-00446_E2_GateDriverPhaseV (C32.1 C42.1 U6.13 U8.13), TIDA-00446_E2_GateDriverPhaseW (C52.1 C62.1 U10.13 U12.13)
~{RESET}: TIDA-00446_E2_GateDriverPhaseU (J2.5 U2.14 U4.14), TIDA-00446_E2_GateDriverPhaseV (U6.14 U8.14), TIDA-00446_E2_GateDriverPhaseW (U10.14 U12.14)
ENABLE: TIDA-00446_E2_GateDriverPhaseU (5 pins), TIDA-00446_E2_GateDriverPhaseV (U5.5 U7.5), TIDA-00446_E2_GateDriverPhaseW (U9.5 U11.5)
PWM_BOT_V: TIDA-00446_E2_GateDriverPhaseU (J2.6), TIDA-00446_E2_GateDriverPhaseV (U8.10)
PWM_BOT_W: TIDA-00446_E2_GateDriverPhaseU (J2.12), TIDA-00446_E2_GateDriverPhaseW (U12.10)
PWM_TOP_V: TIDA-00446_E2_GateDriverPhaseU (J2.8), TIDA-00446_E2_GateDriverPhaseV (U6.10)
PWM_TOP_W: TIDA-00446_E2_GateDriverPhaseU (J2.10), TIDA-00446_E2_GateDriverPhaseW (U10.10)
READY: TIDA-00446_E2_GateDriverPhaseU (6 pins), TIDA-00446_E2_GateDriverPhaseV (C31.1 C41.1 U6.12 U8.12), TIDA-00446_E2_GateDriverPhaseW (C51.1 C61.1 U10.12 U12.12)

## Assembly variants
001: not fitted D5 D11 D19 D25 D31 D37 FID1 FID2 FID3 FID4 FID5 FID6 R4 R11 R18 R23 R28 R33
